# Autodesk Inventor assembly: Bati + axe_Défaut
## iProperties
Shininess: 64.0
Length Units: 11269
Angle Units: 11279
Time Units: 11290
Mass Units: 11283
Length Display Precision: 3
Angle Display Precision: 2
Compacted: True
Created: 2006-11
Part Number: Bati + axe_Défaut
Document SubType Name: Assembly
Designer: profs_sti
Density: 0.0
Volumn: 0.0
Area: 0.0
PropertySet Name: Model Information
Control State: 0
Master: False
Checked Out: False
Author: profs_sti
